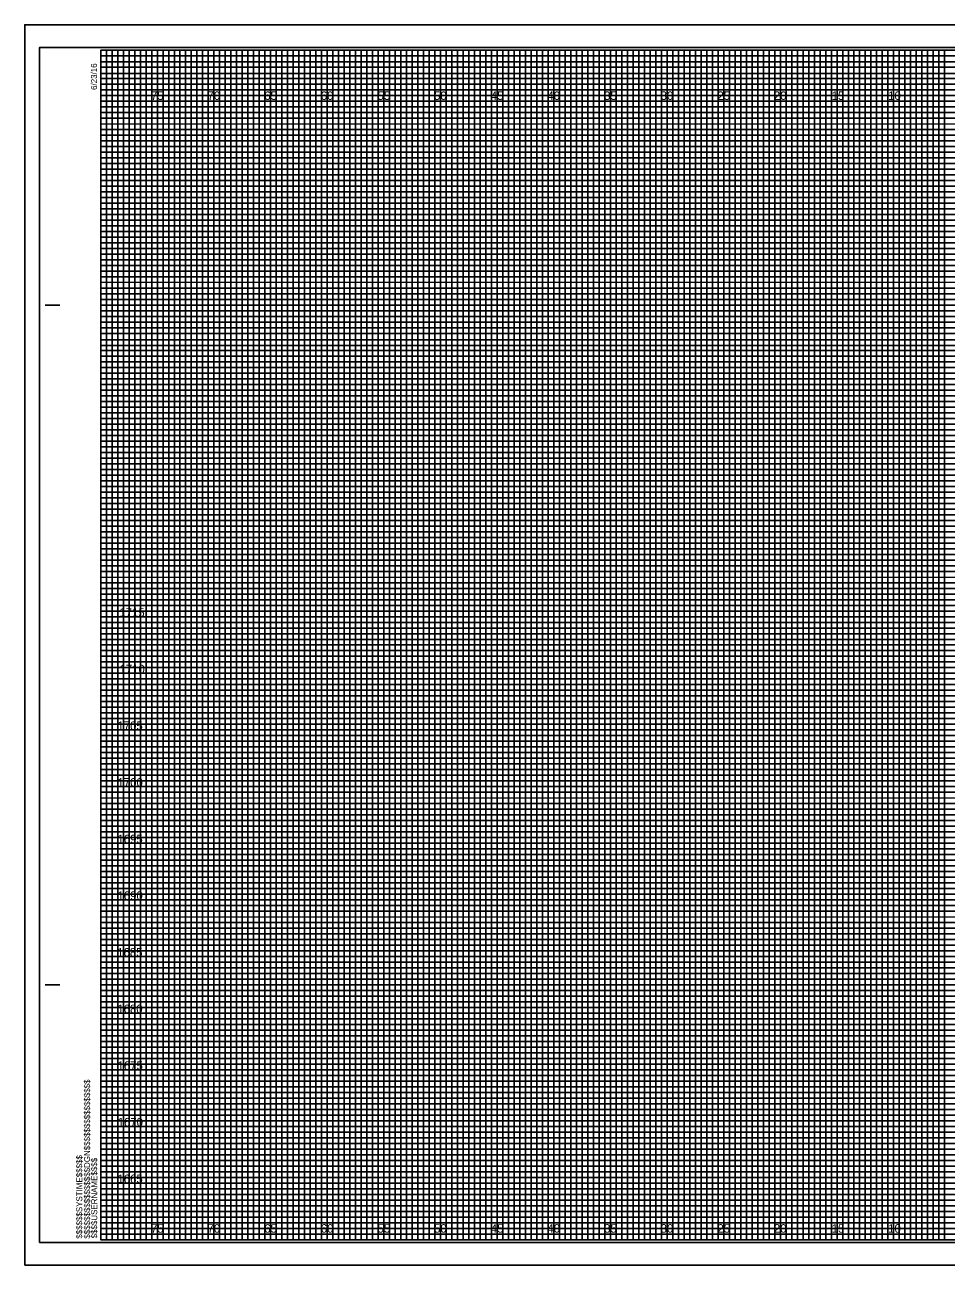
# Model space of a CAD drawing. Extents: x -7 to 162, y -2 to 217.
# Drawn here: x -6.7 to 74.6, y 107.7 to 217.2 of the extents above; entities that cross this region are included whole.
import ezdxf

# ---------------------------------------------------------------- set-up
doc = ezdxf.new("R2010")
doc.units = 0
for name, color, linetype in [('Prop XS Elevation Labels', 7, 'Continuous'), ('Prop XS Offset Labels', 7, 'Continuous'), ('Sheet Cross Section CELL', 7, 'Continuous'), ('Sheet Cross Section Grid Major CELL', 7, 'Continuous'), ('Sheet Cross Section Grid Middle CELL', 7, 'Continuous'), ('Sheet Cross Section Grid Minor 1 CELL', 7, 'Continuous'), ('Sheet Cross Section Grid Minor 2 CELL', 7, 'Continuous'), ('Sheet Cutting Line CELL', 7, 'Continuous'), ('Sheet DOT Grid CELL', 7, 'Continuous'), ('Sheet Plot Border Inside CELL', 7, 'Continuous'), ('Sheet Plot Border Outside CELL', 7, 'Continuous')]:
    doc.layers.add(name, color=color, linetype=linetype)

msp = doc.modelspace()

# ---------------------------------------------------------------- linework, layer by layer
at = {"layer": 'Sheet Cross Section CELL'}
for p, q in [((-4.9, 192.5), (-3.65, 192.5)), ((-4.85, 192.5), (-3.6, 192.5)), ((-4.9, 132.5), (-3.65, 132.5)), ((-4.85, 132.5), (-3.6, 132.5)), ((0, 110), (0, 110)), ((0, 110), (0, 110)), ((0, 110), (0, 110)), ((0, 110), (0, 110)), ((0, 110), (0, 110)), ((0, 110), (0, 110)), ((0, 110), (0, 110))]:
    msp.add_line(p, q, dxfattribs=at)
msp.add_lwpolyline([(160, 215), (0, 215), (0, 110), (160, 110)], close=True, dxfattribs=at)
at = {"layer": 'Sheet Cross Section Grid Major CELL'}
for p, q in [((5, 215), (0, 215)), ((5, 110), (5, 215)), ((15, 215), (10, 215)), ((10, 215), (10, 110)), ((15, 110), (15, 215)), ((25, 215), (20, 215)), ((20, 215), (20, 110)), ((25, 110), (25, 215)), ((35, 215), (30, 215)), ((30, 215), (30, 110)), ((35, 110), (35, 215)), ((45, 215), (40, 215)), ((40, 215), (40, 110)), ((45, 110), (45, 215)), ((55, 215), (50, 215)), ((50, 215), (50, 110)), ((55, 110), (55, 215)), ((65, 215), (60, 215)), ((60, 215), (60, 110)), ((65, 110), (65, 215)), ((75, 215), (70, 215)), ((70, 215), (70, 110)), ((10, 110), (5, 110)), ((20, 110), (15, 110)), ((30, 110), (25, 110)), ((40, 110), (35, 110)), ((50, 110), (45, 110)), ((60, 110), (55, 110)), ((70, 110), (65, 110))]:
    msp.add_line(p, q, dxfattribs=at)
for points in [[(0, 210), (160, 210), (160, 205), (0, 205)], [(0, 200), (160, 200), (160, 195), (0, 195)], [(0, 190), (160, 190), (160, 185), (0, 185)], [(0, 180), (160, 180), (160, 175), (0, 175)], [(0, 170), (160, 170), (160, 165), (0, 165)], [(0, 160), (160, 160), (160, 155), (0, 155)], [(0, 150), (160, 150), (160, 145), (0, 145)], [(0, 140), (160, 140), (160, 135), (0, 135)], [(0, 130), (160, 130), (160, 125), (0, 125)], [(0, 120), (160, 120), (160, 115), (0, 115)]]:
    msp.add_lwpolyline(points, dxfattribs=at)
at = {"layer": 'Sheet Cross Section Grid Middle CELL'}
for points in [[(0, 215), (2.5, 215), (2.5, 110), (7.5, 110), (7.5, 215), (12.5, 215), (12.5, 110), (17.5, 110), (17.5, 215), (22.5, 215), (22.5, 110), (27.5, 110), (27.5, 215), (32.5, 215), (32.5, 110), (37.5, 110), (37.5, 215), (42.5, 215), (42.5, 110), (47.5, 110), (47.5, 215), (52.5, 215), (52.5, 110), (57.5, 110), (57.5, 215), (62.5, 215), (62.5, 110), (67.5, 110), (67.5, 215), (72.5, 215), (72.5, 110), (77.5, 110)], [(0, 212.5), (137.5, 212.5)], [(0, 202.5), (160, 202.5), (160, 207.5), (0, 207.5)], [(0, 192.5), (160, 192.5), (160, 197.5), (0, 197.5)], [(0, 182.5), (160, 182.5), (160, 187.5), (0, 187.5)], [(0, 172.5), (160, 172.5), (160, 177.5), (0, 177.5)], [(0, 162.5), (160, 162.5), (160, 167.5), (0, 167.5)], [(0, 152.5), (160, 152.5), (160, 157.5), (0, 157.5)], [(0, 142.5), (160, 142.5), (160, 147.5), (0, 147.5)], [(0, 132.5), (160, 132.5), (160, 137.5), (0, 137.5)], [(0, 122.5), (160, 122.5), (160, 127.5), (0, 127.5)], [(0, 112.5), (160, 112.5), (160, 117.5), (0, 117.5)]]:
    msp.add_lwpolyline(points, dxfattribs=at)
at = {"layer": 'Sheet Cross Section Grid Minor 1 CELL'}
for p, q in [((0, 214.5), (130, 214.5)), ((130, 213.99), (0, 213.99)), ((0, 213.99), (0, 213.5)), ((0, 213.5), (130, 213.5)), ((130, 212.94), (0, 212.94)), ((0, 212.94), (0, 212)), ((0, 212), (160, 212))]:
    msp.add_line(p, q, dxfattribs=at)
for points in [[(0, 211.5), (135, 211.5), (160, 211.5), (160, 211), (0, 211)], [(0, 210.5), (160, 210.5), (160, 209.5), (0, 209.5)], [(0, 209), (160, 209), (160, 208.5), (0, 208.49)], [(0, 208), (160, 208), (160, 207), (0, 207)], [(0, 206.5), (160, 206.5), (160, 206), (0, 206)], [(0, 205.5), (160, 205.5), (160, 204.5), (0, 204.5)], [(0, 204), (160, 204), (160, 203.5), (0, 203.5)], [(0, 203), (160, 203), (160, 202), (0, 202)], [(0, 201.5), (160, 201.5), (160, 201), (0, 201)], [(0, 200.5), (160, 200.5), (160, 199.5), (0, 199.5)], [(0, 199), (160, 199), (160, 198.5), (0, 198.5)], [(0, 198), (160, 198), (160, 196.97), (160, 196.5), (160, 196), (0, 196)], [(0, 197), (160, 197), (160, 196.5), (0, 196.5)], [(0, 195.5), (160, 195.5), (160, 194.5), (0, 194.52)], [(0, 194.52), (160, 194.5), (160, 194), (0, 194)], [(0, 193.5), (160, 193.5), (160, 193), (0, 193)], [(0, 192), (160, 192), (160, 191.5), (0, 191.5)], [(0, 191), (160, 191), (160, 190.5), (0, 190.5)], [(-0.04, 189.44), (160, 189.44), (160, 188.94), (-0.04, 188.94)], [(0, 188.5), (160, 188.5), (160, 188), (0, 188)], [(0, 187), (160, 187), (160, 186.5), (0, 186.5)], [(0, 186), (160, 186), (160, 185.5), (0, 185.5)], [(0, 184.5), (160, 184.5), (160, 184), (0, 184)], [(0, 183.5), (160, 183.5), (160, 183), (0, 183)], [(0, 182), (160, 182), (160, 181.5), (0, 181.5)], [(0, 181), (160, 181), (160, 180.5), (0, 180.5)], [(0, 179.5), (160, 179.5), (160, 178.99), (0, 179)], [(0, 178.5), (160, 178.5), (160, 178), (0, 178)], [(0, 177), (160, 177), (160, 176.5), (0, 176.5)], [(0, 176), (160, 176), (160, 175.5), (0, 175.5)], [(0, 174.5), (160, 174.5), (160, 174), (0, 174)], [(0, 173.5), (160, 173.5), (160, 173), (0, 173)], [(0, 172), (160, 172), (160, 171.5), (0, 171.5)], [(0, 171), (160, 171), (160, 170.5), (0, 170.5)], [(0, 169.5), (160, 169.5), (160, 169), (0, 169)], [(0, 168.5), (160.03, 168.46), (160, 168), (0, 168)], [(0, 167), (160, 167), (160, 166.5), (0, 166.5)], [(0, 166), (160, 166), (160, 165.5), (0, 165.5)], [(0, 164.5), (160, 164.5), (160, 164), (0, 164)], [(0, 163.5), (160, 163.5), (160, 163), (0, 163)], [(0, 162), (160, 162), (160, 161.5), (0, 161.5)], [(0, 161), (160, 161), (160, 160.5), (0, 160.5)], [(0, 159.5), (160, 159.5), (160, 159), (0, 159)], [(0, 158.5), (160, 158.5), (160, 158), (0, 158)], [(0, 157), (160, 157), (160, 156.5), (0, 156.5)], [(0, 156), (160, 156), (160, 155.5), (0, 155.5)], [(0, 154.5), (160, 154.5), (160, 154), (0, 154)], [(0, 153.5), (160, 153.5), (160, 153), (0, 153)], [(0, 152), (160, 152), (160, 151.5), (0, 151.5)], [(0, 151), (160, 151), (160, 150.5), (0, 150.5)], [(0, 149.5), (160, 149.5), (160, 148.99), (0, 149)], [(0, 148.5), (160, 148.5), (160, 148), (0, 148)], [(0, 147), (160, 147), (160, 146.5), (0, 146.5)], [(0, 146), (160, 146), (160, 145.5), (0, 145.5)], [(0, 144.5), (160, 144.5), (160, 144), (0, 144)], [(0, 143.5), (160, 143.5), (160, 143), (0, 143)], [(0, 142), (160, 142), (160, 141.5), (0, 141.5)], [(0, 141), (160, 141), (160, 140.5), (0, 140.5)], [(0, 139.5), (160, 139.5), (160, 139), (0, 139)], [(0, 138.5), (160.03, 138.46), (160, 138), (0, 138)], [(0, 137), (160, 137), (160, 136.5), (0, 136.5)], [(0, 136), (160, 136), (160, 135.5), (0, 135.5)], [(0, 134.5), (160, 134.5), (160, 134), (0, 134)], [(0, 133.5), (160, 133.5), (160, 133), (0, 133)], [(0, 132), (160, 132), (160, 131.5), (0, 131.5)], [(0, 131), (160, 131), (160, 130.5), (0, 130.5)], [(0, 129.5), (160, 129.5), (160, 129), (0, 129)], [(0, 128.5), (160, 128.5), (160, 128), (0, 128)], [(0, 127), (160, 127), (160, 126.5), (0, 126.5)], [(0, 126), (160, 126), (160, 125.5), (0, 125.5)], [(0, 124.5), (160, 124.5), (160, 124), (0, 124)], [(0, 123.5), (160, 123.5), (160, 123), (0, 123)], [(0, 122), (160, 122), (160, 121.5), (0, 121.5)], [(0, 121), (160, 121), (160, 120.5), (0, 120.5)], [(0, 119.5), (160, 119.5), (160, 119), (0, 119)], [(0, 118.5), (160, 118.5), (160, 118), (0, 118)], [(0, 117), (160, 117), (160, 116.5), (0, 116.5)], [(0, 116), (160, 116), (160, 115.5), (0, 115.5)], [(0, 114.5), (160, 114.5), (160, 114), (0, 114)], [(0, 113.5), (160, 113.5), (160, 113), (0, 113)], [(0, 112), (160, 112), (160, 111.5), (0, 111.5)], [(0, 111), (160, 111), (160, 110.5), (0, 110.5)]]:
    msp.add_lwpolyline(points, dxfattribs=at)
at = {"layer": 'Sheet Cross Section Grid Minor 2 CELL'}
for points in [[(0, 110), (0.5, 110), (0.5, 215), (1, 215), (1, 110)], [(1, 110), (1.5, 110), (1.5, 215), (2, 215), (2, 110)], [(2.5, 110), (3, 110), (3, 215), (3.5, 215), (3.5, 110)], [(3.5, 110), (4, 110), (4, 215), (4.5, 215), (4.5, 110)], [(5, 110), (5.5, 110), (5.5, 215), (6, 215), (6, 110)], [(6, 110), (6.5, 110), (6.5, 215), (7, 215), (7, 110)], [(7.5, 110), (8, 110), (8, 215), (8.5, 215), (8.5, 110)], [(8.5, 110), (9, 110), (9, 215), (9.5, 215), (9.5, 110)], [(10, 110), (10.5, 110), (10.5, 215), (11, 215), (11, 110)], [(11, 110), (11.5, 110), (11.5, 215), (12, 215), (12, 110)], [(12.5, 110), (13, 110), (13, 215), (13.5, 215), (13.5, 110)], [(13.5, 110), (14, 110), (14, 215), (14.5, 215), (14.5, 110)], [(15, 110), (15.5, 110), (15.5, 215), (16, 215), (16, 110)], [(16, 110), (16.5, 110), (16.5, 215), (17, 215), (17, 110)], [(17.5, 110), (18, 110), (18, 215), (18.5, 215), (18.5, 110)], [(18.5, 110), (19, 110), (19, 215), (19.5, 215), (19.5, 110)], [(20, 110), (20.5, 110), (20.5, 215), (21, 215), (21, 110)], [(21, 110), (21.5, 110), (21.5, 215), (22, 215), (22, 110)], [(22.5, 110), (23, 110), (23, 215), (23.5, 215), (23.5, 110)], [(23.5, 110), (24, 110), (24, 215), (24.5, 215), (24.5, 110)], [(25, 110), (25.5, 110), (25.5, 215), (26, 215), (26, 110)], [(26, 110), (26.5, 110), (26.5, 215), (27, 215), (27, 110)], [(27.5, 110), (28, 110), (28, 215), (28.5, 215), (28.5, 110)], [(28.5, 110), (29, 110), (29, 215), (29.5, 215), (29.5, 110)], [(30, 110), (30.5, 110), (30.5, 215), (31, 215), (31, 110)], [(31, 110), (31.5, 110), (31.5, 215), (32, 215), (32, 110)], [(32.5, 110), (33, 110), (33, 215), (33.5, 215), (33.5, 110)], [(33.5, 110), (34, 110), (34, 215), (34.5, 215), (34.5, 110)], [(35, 110), (35.5, 110), (35.5, 215), (36, 215), (36, 110)], [(36, 110), (36.5, 110), (36.5, 215), (37, 215), (37, 110)], [(37.5, 110), (38, 110), (38, 215), (38.5, 215), (38.5, 110)], [(38.5, 110), (39, 110), (39, 215), (39.5, 215), (39.5, 110)], [(40, 110), (40.5, 110), (40.5, 215), (41, 215), (41, 110)], [(41, 110), (41.5, 110), (41.5, 215), (42, 215), (42, 110)], [(42.5, 110), (43, 110), (43, 215), (43.5, 215), (43.5, 110)], [(43.5, 110), (44, 110), (44, 215), (44.5, 215), (44.5, 110)], [(45, 110), (45.5, 110), (45.5, 215), (46, 215), (46, 110)], [(46, 110), (46.5, 110), (46.5, 215), (47, 215), (47, 110)], [(47.5, 110), (48, 110), (48, 215), (48.5, 215), (48.5, 110)], [(48.5, 110), (49, 110), (49, 215), (49.5, 215), (49.5, 110)], [(50, 110), (50.5, 110), (50.5, 215), (51, 215), (51, 110)], [(51, 110), (51.5, 110), (51.5, 215), (52, 215), (52, 110)], [(52.5, 110), (53, 110), (53, 215), (53.5, 215), (53.5, 110)], [(53.5, 110), (54, 110), (54, 215), (54.5, 215), (54.5, 110)], [(55, 110), (55.5, 110), (55.5, 215), (56, 215), (56, 110)], [(56, 110), (56.5, 110), (56.5, 215), (57, 215), (57, 110)], [(57.5, 110), (58, 110), (58, 215), (58.5, 215), (58.5, 110)], [(58.5, 110), (59, 110), (59, 215), (59.5, 215), (59.5, 110)], [(60, 110), (60.5, 110), (60.5, 215), (61, 215), (61, 110)], [(61, 110), (61.5, 110), (61.5, 215), (62, 215), (62, 110)], [(62.5, 110), (63, 110), (63, 215), (63.5, 215), (63.5, 110)], [(63.5, 110), (64, 110), (64, 215), (64.5, 215), (64.5, 110)], [(65, 110), (65.5, 110), (65.5, 215), (66, 215), (66, 110)], [(66, 110), (66.5, 110), (66.5, 215), (67, 215), (67, 110)], [(67.5, 110), (68, 110), (68, 215), (68.5, 215), (68.5, 110)], [(68.5, 110), (69, 110), (69, 215), (69.5, 215), (69.5, 110)], [(70, 110), (70.5, 110), (70.5, 215), (71, 215), (71, 110)], [(71, 110), (71.5, 110), (71.5, 215), (72, 215), (72, 110)], [(72.5, 110), (73, 110), (73, 215), (73.5, 215), (73.5, 110)], [(73.5, 110), (74, 110), (74, 215), (74.5, 215), (74.5, 110)]]:
    msp.add_lwpolyline(points, dxfattribs=at)
at = {"layer": 'Sheet Cutting Line CELL'}
for p, q in [((161.65, 217.25), (-6.7, 217.25)), ((-6.7, 217.25), (-6.7, 107.75)), ((-6.7, 107.75), (161.65, 107.75))]:
    msp.add_line(p, q, dxfattribs=at)
at = {"layer": 'Sheet DOT Grid CELL'}
for p, q in [((5, 110), (5, 215)), ((10, 110), (10, 215)), ((15, 110), (15, 215)), ((20, 110), (20, 215)), ((25, 110), (25, 215)), ((30, 110), (30, 215)), ((35, 110), (35, 215)), ((40, 110), (40, 215)), ((45, 110), (45, 215)), ((50, 110), (50, 215)), ((55, 110), (55, 215)), ((60, 110), (60, 215)), ((65, 110), (65, 215)), ((70, 110), (70, 215)), ((0, 210), (160, 210)), ((0, 205), (160, 205)), ((0, 200), (160, 200)), ((0, 195), (160, 195)), ((0, 190), (160, 190)), ((0, 185), (160, 185)), ((0, 180), (160, 180)), ((0, 175), (160, 175)), ((0, 170), (160, 170)), ((0, 165), (160, 165)), ((0, 160), (160, 160)), ((0, 155), (160, 155)), ((0, 150), (160, 150)), ((0, 145), (160, 145)), ((0, 140), (160, 140)), ((0, 135), (160, 135)), ((0, 130), (160, 130)), ((0, 125), (160, 125)), ((0, 120), (160, 120)), ((0, 115), (160, 115))]:
    msp.add_line(p, q, dxfattribs=at)
at = {"layer": 'Sheet Plot Border Inside CELL'}
msp.add_lwpolyline([(-5.4, 109.75), (161.2, 109.75), (161.2, 215.25), (-5.4, 215.25)], close=True, dxfattribs=at)
at = {"layer": 'Sheet Plot Border Outside CELL'}
msp.add_lwpolyline([(-6.7, 107.75), (161.65, 107.75), (161.65, 217.25), (-6.7, 217.25)], close=True, dxfattribs=at)

# ---------------------------------------------------------------- texts
at = {"layer": 'Prop XS Elevation Labels'}
for s, p in [('1715', (1.65, 165)), ('1710', (1.66, 160)), ('1705', (1.48, 155)), ('1700', (1.49, 150)), ('1695', (1.48, 145)), ('1690', (1.48, 140)), ('1685', (1.46, 135)), ('1680', (1.47, 130)), ('1675', (1.49, 125)), ('1670', (1.5, 120)), ('1665', (1.48, 115))]:
    msp.add_text(s, height=0.75, dxfattribs=at).set_placement(p)
at = {"layer": 'Prop XS Offset Labels'}
for s, p in [('75', (4.44, 210.62)), ('70', (9.43, 210.62)), ('65', (14.44, 210.62)), ('60', (19.43, 210.62)), ('55', (24.44, 210.62)), ('50', (29.43, 210.62)), ('45', (34.44, 210.62)), ('40', (39.43, 210.62)), ('35', (44.44, 210.62)), ('30', (49.43, 210.62)), ('25', (54.44, 210.62)), ('20', (59.43, 210.62)), ('15', (64.53, 210.62)), ('10', (69.52, 210.62)), ('75', (4.44, 110.62)), ('70', (9.43, 110.62)), ('65', (14.44, 110.62)), ('60', (19.43, 110.62)), ('55', (24.44, 110.62)), ('50', (29.43, 110.62)), ('45', (34.44, 110.62)), ('40', (39.43, 110.62)), ('35', (44.44, 110.62)), ('30', (49.43, 110.62)), ('25', (54.44, 110.62)), ('20', (59.43, 110.62)), ('15', (64.53, 110.62)), ('10', (69.52, 110.62))]:
    msp.add_text(s, height=0.75, dxfattribs=at).set_placement(p)
at = {"layer": 'Sheet Cross Section CELL'}
for s, p in [('6/23/16', (-0.33, 211.5)), ('$$$$$$$$$$$$$$$$DGN$$$$$$$$$$$$$$$$', (-0.94, 110.09)), ('$$$$$$SYSTIME$$$$$', (-1.63, 110.09)), ('$$$$USERNAME$$$$', (-0.31, 110.12))]:
    msp.add_text(s, height=0.525, rotation=90, dxfattribs=at).set_placement(p)

doc.saveas('drawing.dxf')
